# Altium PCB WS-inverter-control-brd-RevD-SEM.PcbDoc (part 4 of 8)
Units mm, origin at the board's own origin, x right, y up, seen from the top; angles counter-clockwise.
Board outline 270 x 105.92 mm, 6 copper layers (Top Layer, Int1 (Sign), Int2 (PWR), Int3 (GND), Int4 (Sign), Bottom Layer), stack 1.509 mm thick; 709 components, 375 nets, 2377 pads, 1332 vias.
Unrouted connection lines stored in the file: 55.
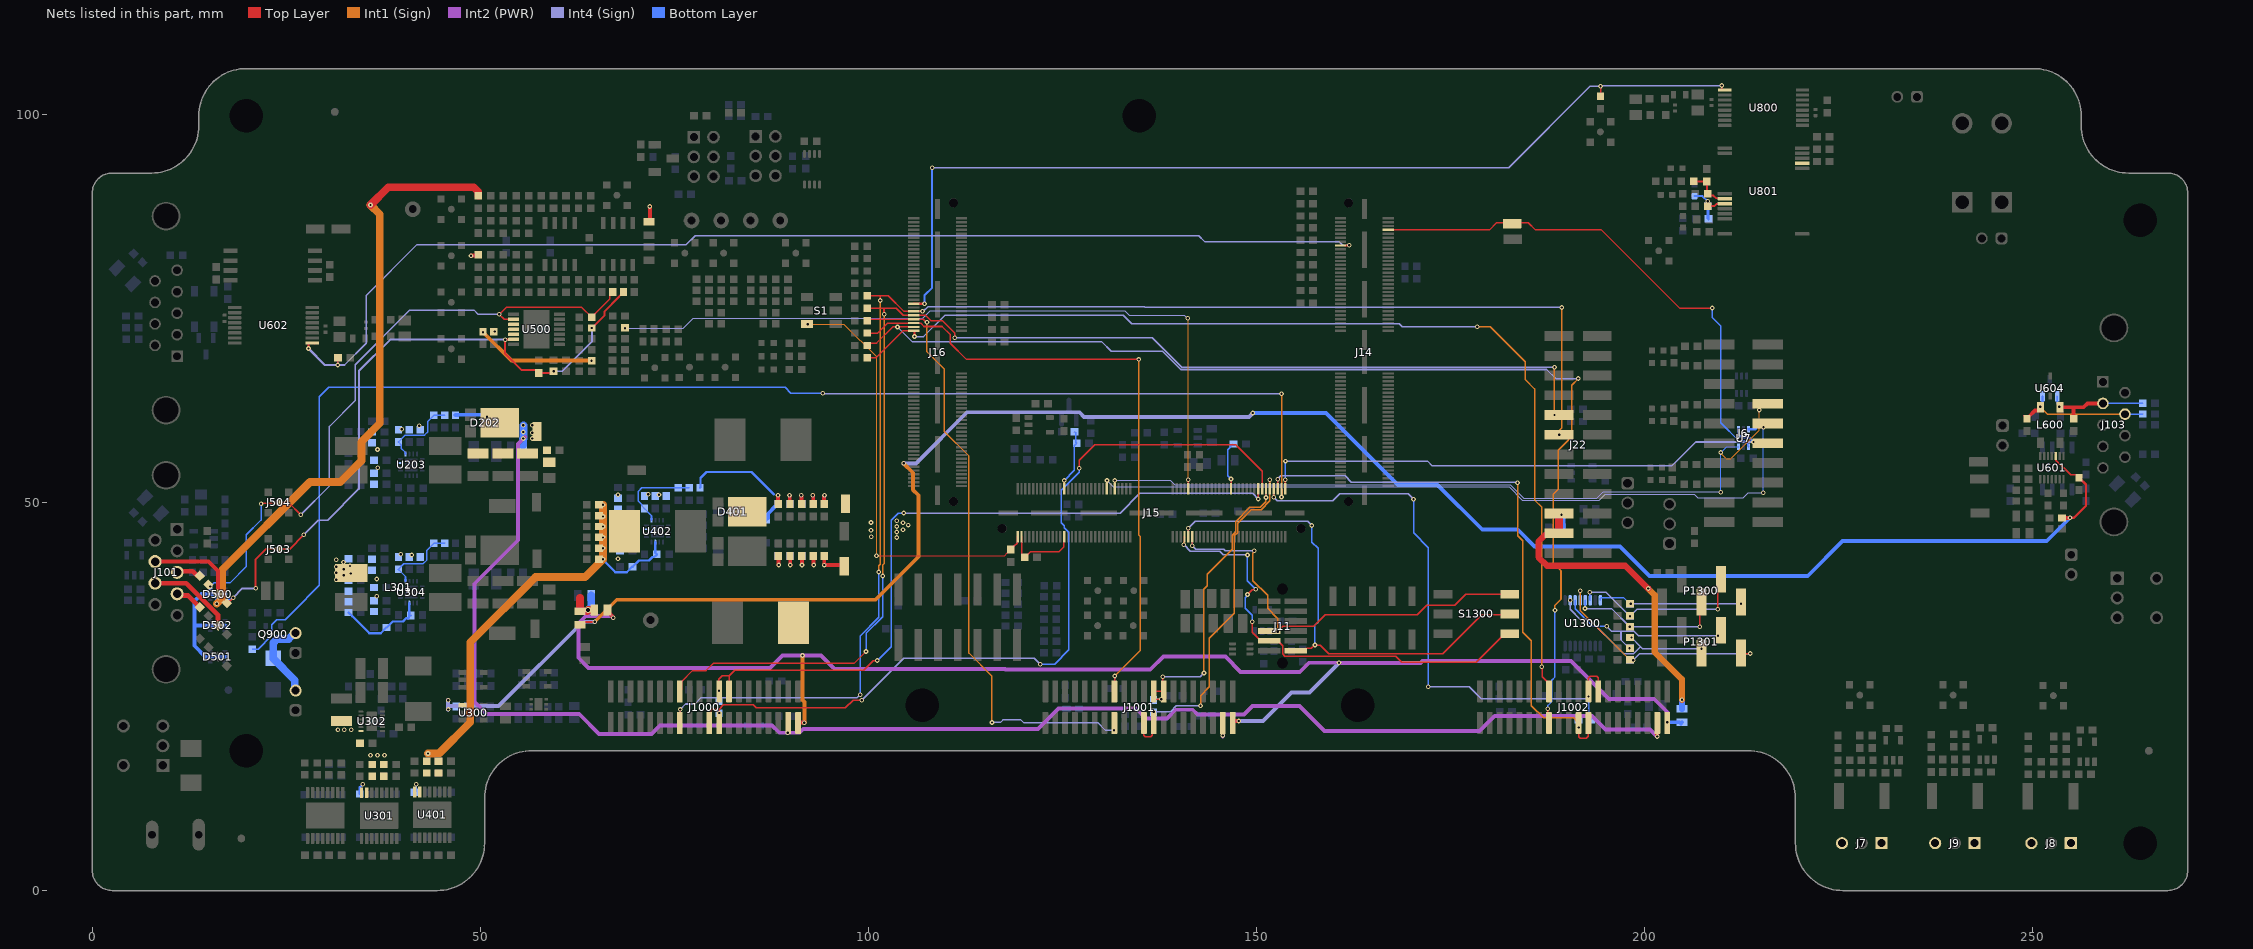
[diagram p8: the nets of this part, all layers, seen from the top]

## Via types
v1: diameter 0.6, hole 0.3, Top Layer to Bottom Layer, tented both sides, 1302 vias
v2: diameter 0.5, hole 0.2, Top Layer to Bottom Layer, 17 vias
v3: diameter 0.6, hole 0.3, Top Layer to Bottom Layer, 12 vias
v4: diameter 0.8, hole 0.5, Top Layer to Bottom Layer, tented both sides, 1 vias

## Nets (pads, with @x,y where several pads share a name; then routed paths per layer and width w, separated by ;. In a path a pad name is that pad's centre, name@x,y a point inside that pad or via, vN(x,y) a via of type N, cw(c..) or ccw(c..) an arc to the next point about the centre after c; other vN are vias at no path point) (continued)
+12V_L: C302.1 C303.1 C304.1 C305.1 C306.1 C307.1 C313.1 C317.1 C318.1 C319.1 C320.1 C321.1 C322.2 C328.1 C345.1 C611.2 L301.1 R300.2 R310.2 R619.2 Rjump12v.2 U300.1 U301.15 U301.16 U302.10 U302.12 U304.3 U601.10 | length 276.3
  Top Layer w0.25: Rjump12v.2@62.843,34.256 62.973,34.256 63.343,34.626 64.733,34.626 v1(64.743,34.636) ; U601.10@253,56 253.025,55.975 253.025,55.455 254.905,53.575 255.65,53.575 256,53.225 C611.2@256,53.2
  Top Layer w0.3: R619.2@253.8,48 v1@254.726,48 ; v1(254.843,48.036) 255.343,48.036 256.893,49.586 256.893,52.307 C611.2@256,53.2
  Top Layer w0.5: R619.2@253.8,48 253.825,48 254.807,48 v1(254.843,48.036)
  Int1 (Sign) w0.5: v1(64.743,34.636) 67.579,37.472 100.909,37.472 106.443,43.006 106.443,50.935 105.743,51.635 105.743,53.836 v1(104.543,55.036)
  Int4 (Sign) w0.5: v1(45.843,23.336) 45.843,23.754 ; v1(45.843,24.536) 45.843,23.754 ; v1(64.743,34.636) 63.233,34.636 52.351,23.754 45.843,23.754 ; v1(104.543,55.036) 106.127,55.036 112.715,61.625 127.209,61.625 127.797,61.036 149.043,61.036 v1(149.543,61.536)
  Bottom Layer w0.3: C317.1@33,35.825 33.025,35.825 33.489,35.361 33.5,35.361 35.699,33.161 37.15,33.161 37.875,33.886 R310.2@37.9,33.886 37.925,33.886 38.712,34.674 40.021,34.674 40.434,35.086 40.718,35.086 40.807,35.175 40.807,35.436 C328.1@41.043,35.436 ; R300.2@34.457,12.443 34.457,13.292 v1(34.858,13.693) ; C328.1@40.85,35.493 U304.3@40.85,37.05
  Bottom Layer w0.5: v1(149.543,61.536) 158.943,61.536 168.221,52.259 173.345,52.259 179.107,46.496 183.68,46.496 185.84,44.336 196.843,44.336 200.643,40.536 221.043,40.536 225.543,45.036 251.843,45.036 v1(254.843,48.036)
  other v1: 35.843,17.436 36.743,17.436 37.643,17.436 31.643,20.736 32.443,20.736 33.343,20.736 31.443,40.036 32.404,40.625 33.309,40.846 31.443,40.936 32.404,41.385 31.443,41.736 33.202,41.825 32.357,42.29 31.443,42.636
+12V_LEM: C406.1 C407.1 C408.1 C409.1 C413.1 C414.1 C415.1 C416.1 C417.1 C418.1 C429.1 L400.1 R400.2 R425.2 U401.15 U401.16 U402.3 | length 57.4
  Int1 (Sign) w1: v1(43.256,17.656) 44.663,17.656 48.7,21.694 48.7,31.994 57.095,40.389 63.489,40.389 v1(65.8,42.7) v1(65.8,44.1) v1(65.8,49.7)
  Bottom Layer w0.2: R400.2@41.5,12.643 41.749,12.892 v1(41.749,13.703)
  Bottom Layer w0.3: v1(65.8,42.7) 65.857,42.643 65.857,42.553 67.399,41.011 68.85,41.011 69.575,41.736 R425.2@69.6,41.736 69.625,41.736 70.425,42.536 71.744,42.536 72.184,42.976 72.242,42.976 72.253,42.986 72.418,42.986 C429.1@72.743,43.311 ; U402.3@72.55,44.9 72.55,43.53 C429.1@72.743,43.336
  other v1: 65.8,45.5 65.8,46.9 65.8,48.204
+15V: C412.1 C421.1 C422.1 C423.2 C424.2 C425.2 C426.2 C427.2 C428.2 C504.1 C505.1 D401.3 D500.2 D500.5 D501.2 D501.5 D502.2 D502.5 J7.1 J8.1 J9.1 R426.2 R505.2 R530.1 R541.1 R549.1 TP401.1 U500.10 U500.11 U500.12 | length 137.8
  Top Layer w0.5: v1(48.802,81.795) 48.843,81.836 49.663,81.836 R530.1@49.738,81.911 ; v1(64.32,68.279) 64.337,68.279 R505.2@64.344,68.286 ; R541.1@71.738,86.161 71.843,86.266 v1(71.843,88.136) ; v1(88.343,50.936) 88.362,50.917 88.362,49.838 C428.2@88.4,49.8 ; v1(89.843,50.936) 89.862,50.917 89.862,49.838 C427.2@89.9,49.8 ; v1(91.343,50.936) 91.343,50.909 91.4,50.853 C426.2@91.4,49.8 ; v1(92.843,50.936) 92.843,50.909 92.9,50.853 C422.1@92.9,49.8 ; C421.1@94.3,49.8 94.3,50.866 94.343,50.909 v1(94.343,50.936)
  Top Layer w1: v1(35.843,88.336) 38.143,90.636 49.153,90.636 49.738,90.051 R549.1@49.738,89.511
  Int2 (PWR) w0.5: v1@64.313,68.286 v1(64.32,68.279)
  Int1 (Sign) w0.5: v1(50.343,71.933) 53.997,68.279 v1(64.32,68.279)
  Int1 (Sign) w1: v1(16.036,36.943) 16.746,37.653 16.746,41.339 28.043,52.636 31.943,52.636 34.675,55.368 34.675,57.842 37.043,60.21 37.043,87.136 v1(35.843,88.336)
  Bottom Layer w0.3: R426.2@78.3,51.9 78.356,51.956 78.356,53.149 79.143,53.936 84.943,53.936 87.843,51.036
  Bottom Layer w0.5: v1(16.036,36.943) 16.036,38.123 16.113,38.199 ; D501.5@17.1,30.119 D501.2@15.2,30.119 15.193,30.112 14.567,30.112 13.143,31.536 13.143,34.159 ; D502.5@17.1,34.159 D502.2@15.2,34.159 13.143,34.159 ; D500.5@17.1,38.199 16.113,38.199 ; C412.1@86.8,47.8 86.825,47.8 87.05,48.025 87.05,48.545 88.055,49.55 88.175,49.55 88.4,49.775 C423.2@88.4,49.8 ; 13.143,34.159 13.143,37.312 14.03,38.199 D500.2@15.2,38.199 16.113,38.199
  other v1: 51.843,72.033
+24V_H: C219.1 C230.1 C231.1 C232.1 C233.1 C234.1 D202.3 J1000.37 J1001.37 J1002.37 R244.2 TP201.1 | length 212.2
  Top Layer w0.5: v1(89.627,20.329) 89.646,20.348 89.646,21.566 J1000.37@89.669,21.588 ; v1(145.669,19.976) J1001.37@145.669,21.588 ; v1(201.643,19.836) 201.643,21.563 J1002.37@201.669,21.588
  Int2 (PWR) w0.5: v1@55.743,58.436 v1(55.543,58.236) 54.843,57.536 54.843,45.136 49.243,39.536 49.243,24.282 50.786,22.739 62.741,22.739 65.293,20.186 72.029,20.186 73.129,21.286 87.581,21.286 88.538,20.329 91.136,20.329 91.612,20.806 121.872,20.806 124.514,23.448 134.514,23.448 135.775,22.186 138.493,22.186 139.605,23.298 141.8,23.298 142.393,22.704 145.643,22.704 ; v1@145.669,19.862 v1(145.669,19.976) 145.669,22.679 145.643,22.704 ; v1(201.643,19.836) 200.727,20.753 194.978,20.753 193.257,22.473 180.704,22.473 178.767,20.536 158.763,20.536 155.531,23.768 149.475,23.768 148.411,22.704 145.643,22.704
  Bottom Layer w0.5: R244.2@46.8,61.25 47.123,61.25 47.173,61.3 50.58,61.3 v1(50.843,61.036)
  Bottom Layer w1: C219.1@55.5,57.4 55.5,58.193 v1(55.543,58.236) v1(55.543,59.086) v1(55.543,59.936)
  other v1: 56.7,58.249 56.7,58.993 56.7,59.934
+24V_L: R114.2 Rjump12v.1 Rjumppre.1 | length 5.7
  Top Layer w1: 62.843,37.736 Rjump12v.1@62.843,35.986 62.848,35.991 63.748,35.991 v4(63.893,36.136) R114.2@64.663,36.136
  Bottom Layer w1: v4(63.893,36.136) 64.288,36.531 64.288,38.031 Rjumppre.1@64.293,38.036
+24V_L_SF: J1000.39 J1001.39 J1002.39 R113.1 R114.1 | length 187.7
  Top Layer w0.5: R114.1@66.393,36.136 66.393,35.931 67.104,35.221 v1(67.104,35.161) ; J1000.39@90.939,21.588 90.987,21.636 v1(91.743,21.636) ; J1001.39@146.939,21.588 146.939,21.716 147.059,21.836 v1(147.743,21.836) ; J1002.39@202.896,21.751 v1(202.961,21.686)
  Int2 (PWR) w0.5: v1(67.104,35.161) 66.909,35.356 63.582,35.356 62.643,34.417 62.643,29.987 63.938,28.692 87.337,28.692 88.922,30.276 v1(91.504,30.276) 93.872,30.276 95.612,28.536 117.601,28.536 117.682,28.455 136.324,28.455 138.004,30.136 146,30.136 147.961,28.175 155.587,28.175 156.758,29.346 v1@160.643,29.346 ; v1(160.643,29.336) 171.133,29.336 171.393,29.596 190.518,29.596 195.452,24.663 201.266,24.663 202.961,22.968 v1(202.961,21.686)
  Int1 (Sign) w0.5: v1(91.504,30.276) 91.504,24.538 91.743,24.298 v1(91.743,21.636)
  Int4 (Sign) w0.5: v1(147.743,21.836) 150.843,21.836 154.543,25.536 156.843,25.536 v1(160.643,29.336)
  Bottom Layer w0.5: v1(202.961,21.686) 204.543,21.686 204.693,21.536 R113.1@204.843,21.686
+24V_L_SMCU: C17.1 C18.1 J22.19 J22.21 R113.2 | length 42.2
  Top Layer w0.8: J22.21@188.993,46.036 188.758,45.801 187.176,45.801 186.334,44.96 186.334,42.972 187.447,41.859 197.536,41.859 v1(200.482,38.913)
  Top Layer w1: J22.21@188.993,46.036 J22.19@188.993,48.418 ; J22.19@189.312,48.418 v1(189.312,48.431)
  Int1 (Sign) w0.8: v1(200.482,38.913) 201.328,38.067 201.328,30.727 204.826,27.229 v1@204.826,24.571
  Bottom Layer w0.18: R113.2@204.829,23.43 R113.2@204.843,23.416
  Bottom Layer w0.8: R113.2@204.829,23.43 v1(204.829,24.567)
  Bottom Layer w1: v1(189.312,48.431) C18.1@189.318,48.436 ; C17.1@189.318,46.836 C18.1@189.318,48.431
-15V: C435.2 C436.2 C437.1 C438.1 C439.1 C440.1 C441.1 C442.1 J7.3 J8.3 J9.3 L402.2 TP404.1 | length 8.6
  Top Layer w0.5: C442.1@88.4,43.1 88.424,43.076 88.424,41.956 v1(88.443,41.936) ; C441.1@89.9,43.1 89.924,43.076 89.924,41.956 v1(89.943,41.936) ; C440.1@91.4,43.1 91.424,43.076 91.424,41.956 v1(91.443,41.936) ; C436.2@92.9,43.1 92.924,43.076 92.924,41.956 v1(92.943,41.936) ; C435.2@94.3,43.1 94.309,43.091 v1(94.309,41.935) 96.765,41.935 TP404.1@96.9,41.8
  Int2 (PWR) w1: J9.3@237.443,6.083 J9.3@237.463,6.103
  other v1: 103.652,45.489 100.352,45.589 103.652,46.189 100.343,46.436 104.452,46.489 103.646,46.916 105.152,47.089 104.452,47.389 100.328,47.416 103.662,47.647
AD_H_A: J16.52 J22.9 J1000.16 R43.2 | length 170.2
  Top Layer w0.2: J1000.16@75.699,25.653 75.969,25.924 75.969,26.962 77.343,28.336 79.088,28.336 80.058,29.306 98.203,29.306 v1(99.698,30.801) ; R43.2@99.843,75.036 102.014,75.036 ; v1(102.043,74.236) 102.014,74.266 102.014,75.036 ; J16.52@105.838,74.122 104.504,74.122 103.6,75.026 102.14,75.026 102.129,75.036 102.014,75.036 ; J16.52@105.843,74.126 107.36,74.126 108.096,73.39 109.581,73.39 111.143,71.829 v1(111.143,71.236) ; v1(188.401,61.278) J22.9@188.443,61.236
  Int1 (Sign) w0.2: v1(101.843,40.536) 101.843,41.936 102.043,42.136 v1(102.043,74.236) ; v1(188.401,61.278) v1(188.401,67.436)
  Int4 (Sign) w0.2: v1(111.143,71.236) 136.572,71.236 140.372,67.436 v1(188.401,67.436)
  Bottom Layer w0.2: v1(99.698,30.801) 99.698,33.139 101.843,35.284 v1(101.843,40.536)
AD_H_B: J16.56 J1001.16 R44.2 | length 82.4
  Top Layer w0.2: R44.2@99.843,71.836 101.207,71.836 102.493,73.122 J16.56@105.838,73.122 105.845,73.115 106.733,73.115 107.167,72.681 109.498,72.681 110.543,71.636 110.543,70.526 112.633,68.436 v1(134.843,68.436) ; J1001.16@131.699,25.653 131.743,25.698 v1(131.743,27.636)
  Int1 (Sign) w0.2: v1(131.743,27.636) 135.043,30.936 135.043,45.605 134.843,45.805 v1(134.843,68.436)
AD_H_C: J16.60 J1002.16 R45.2 | length 134.3
  Top Layer w0.2: R45.2@99.843,68.636 100.985,68.636 104.471,72.122 J16.60@105.838,72.122 105.887,72.122 105.939,72.069 v1(105.939,71.383) ; v1(186.756,28.852) 186.82,28.788 186.82,27.56 187.543,26.836 187.543,25.809 J1002.16@187.699,25.653
  Int1 (Sign) w0.2: v1(178.443,72.636) 180.133,72.636 184.643,68.126 184.643,65.836 185.843,64.636 185.843,50.336 186.756,49.423 v1(186.756,28.852)
  Int4 (Sign) w0.2: v1(105.939,71.383) 107.116,71.383 109.876,74.142 132.837,74.142 133.943,73.036 168.4,73.036 168.8,72.636 v1(178.443,72.636)
AD_L_A: J16.50 J22.11 J1000.15 R46.2 | length 185.4
  Top Layer w0.2: J1000.15@75.699,21.588 75.743,21.633 v1(75.743,23.336) ; R46.2@99.843,76.636 101.543,76.636 ; v1(101.543,76.036) 101.543,76.636 ; v1(106.974,74.65) 106.96,74.636 105.852,74.636 J16.50@105.838,74.622 104.58,74.622 102.566,76.636 101.543,76.636 ; J22.11@188.993,58.736 v1(189.016,58.736)
  Int1 (Sign) w0.2: v1(101.343,41.036) 101.343,41.836 101.543,42.036 v1(101.543,76.036) ; v1(189.016,58.736) 189.016,59.276 189.343,59.603 v1(189.343,75.136)
  Int4 (Sign) w0.2: v1(75.743,23.336) 76.443,24.036 77.643,24.036 78.443,24.836 98.543,24.836 v1(98.943,25.236) ; v1(106.974,74.65) 107.082,74.65 107.669,75.236 135.55,75.236 135.65,75.136 v1(189.343,75.136)
  Bottom Layer w0.2: v1(98.943,25.236) 98.943,32.808 101.343,35.208 v1(101.343,41.036)
AD_L_B: J16.54 J1001.15 R47.2 | length 79.8
  Top Layer w0.2: R47.2@99.843,73.436 100.029,73.622 J16.54@105.276,73.622 ; J16.54@105.838,73.622 107.08,73.622 107.466,73.236 v1(107.543,73.236) ; v1(131.653,20.635) 131.699,20.681 J1001.15@131.699,21.588
  Int1 (Sign) w0.2: v1(107.543,73.236) 107.543,69.436 109.747,67.232 109.747,59.183 112.953,55.977 112.953,30.595 115.889,27.659 115.889,21.656 v1(115.924,21.656)
  Int4 (Sign) w0.2: v1(115.924,21.656) 117.017,21.656 117.347,21.986 119.649,21.986 119.998,21.636 129.543,21.636 130.545,20.635 v1(131.653,20.635)
AD_L_C: J16.58 J1002.15 R48.2 | length 144.2
  Top Layer w0.2: R48.2@99.843,70.236 100.147,70.54 101.047,70.54 103.129,72.622 v1(103.743,72.622) J16.58@105.573,72.622 ; v1(187.543,23.416) 187.543,21.744 J1002.15@187.699,21.588
  Int1 (Sign) w0.2: v1(188.471,36.112) 188.471,36.764 189.25,37.543 189.25,41.219 188.253,42.216 188.253,51.049 188.899,51.696 188.899,56.743 190.629,58.472 190.629,65.122 v1(191.489,65.982)
  Int4 (Sign) w0.2: v1(103.743,72.622) 105.629,70.736 130.054,70.736 131.298,69.493 137.887,69.493 139.343,68.036 139.348,68.036 140.248,67.136 187.389,67.136 188.589,65.936 191.443,65.936 v1(191.489,65.982)
  Bottom Layer w0.2: v1(187.543,23.416) 187.563,23.436 187.563,23.845 188.069,24.351 188.069,27.099 188.471,27.502 v1(188.471,36.112)
ADJ_NC_9: U801.3
AGND_A: C235.2 C238.2 C239.2 NT200.2 R247.1 R248.1 R249.1 R250.1 R251.1 U203.7
  other v1: 36.765,54.475 36.743,56.836 39.851,59.431 42.112,59.886
AGND_B: C337.2 C343.2 C344.2 NT300.2 R314.1 R315.1 R316.1 R317.1 R318.1 U304.7
  other v1: 36.643,37.936 36.643,40.136 41.143,43.236 39.743,43.336
AGND_C: C432.2 C444.2 C445.2 NT400.2 R428.1 R431.1 R432.1 R433.1 R434.1 U402.7
  other v1: 67.743,42.736 73.019,50.98 67.743,51.011 71.646,51.047
Alert_A: J6.5 J15.2 U7.1 | length 69
  Top Layer w0.18: J15.2@153.733,51.757 v1(153.733,52.926)
  Top Layer w0.3: v1(214.063,57.798) 214.169,57.692 J6.5@214.614,57.692
  Int4 (Sign) w0.2: v1(153.743,55.336) 172.043,55.336 172.638,54.742 203.548,54.742 206.605,57.798 v1(214.063,57.798)
  Bottom Layer w0.2: v1(153.733,52.926) 153.738,52.931 153.738,55.331 v1(153.743,55.336)
  Bottom Layer w0.3: U7.1@212.123,59.424 212.173,59.374 212.173,58.724 212.53,58.367 213.493,58.367 v1(214.063,57.798)
Alert_B: J6.6 J15.74 U7.3 | length 99.1
  Top Layer w0.18: J15.74@130.733,51.757 130.738,51.762 130.738,52.831 v1(130.743,52.836)
  Top Layer w0.3: J6.6@214.298,59.959 214.566,59.69 v1(215.346,59.69)
  Int4 (Sign) w0.16: v1(130.743,52.836) 131.581,51.999 182.581,51.999 184.283,50.296 194.197,50.296 194.937,51.036 206.443,51.036 206.843,50.636 212.743,50.636 213.356,51.249 v1(215.328,51.249)
  Bottom Layer w0.16: v1(215.328,51.249) 215.337,51.258 215.337,59.681 v1(215.346,59.69)
  Bottom Layer w0.3: U7.3@213.423,59.424 214.266,59.424 214.533,59.69 v1(215.346,59.69)
Alert_C: J6.7 J15.70 U7.6 | length 98.1
  Top Layer w0.18: J15.70@131.733,51.757 131.738,51.762 131.738,52.831 v1(131.743,52.836)
  Top Layer w0.3: v1(214.814,61.928) J6.7@214.814,62.392
  Int1 (Sign) w0.16: v1(209.843,56.436) 209.843,56.336 210.523,55.656 211.142,55.656 214.814,59.329 v1(214.814,61.928)
  Int4 (Sign) w0.16: v1(131.743,52.836) 138.885,52.836 139.463,52.259 182.721,52.259 184.423,50.556 193.885,50.556 194.692,51.363 209.816,51.363 v1(209.843,51.336)
  Bottom Layer w0.16: v1(209.843,51.336) v1(209.843,56.436) 210.581,57.174 U7.6@212.123,57.174
Alert_tmcs: J14.114 TP_alert.1 U7.4 | length 66.9
  Top Layer w0.2: J14.114@167.001,85.122 180.029,85.122 180.943,86.036 182.943,86.036 185.043,86.036 185.958,85.122 194.458,85.122 204.524,75.056 v1(208.743,75.056)
  Bottom Layer w0.2: v1(208.743,75.056) 208.743,73.836 209.843,72.736 209.843,60.288 212.198,57.933 212.936,57.933 213.323,57.547 213.323,57.278 U7.4@213.425,57.176
ALM_EXC+_5: C501.2 D500.6 J503.1 R500.2 R503.1 R509.1 R512.2 U500.13 | length 87.2
  Top Layer w0.25: R503.1@17.331,37.049 17.455,37.049 v1(18.143,37.736) ; v1(21.043,38.936) 21.043,42.682 22.361,44 J503.1@24,44 25.407,44 v1(27.248,45.841) ; U500.13@54.288,71.011 54.275,70.998 53.205,70.998 v1(53.191,70.984) 53.191,69.183 55.304,67.07 57.15,67.07 57.5,66.72 C501.2@57.5,66.7 R500.2@59.727,66.7 ; v1(64.369,72.486) 64.969,73.086 64.976,73.086 65.999,74.11 65.999,74.64 67.838,76.48 67.838,76.486 68.438,77.086 R512.2@68.438,77.111
  Int4 (Sign) w0.25: v1(18.143,37.736) 19.325,38.919 21.025,38.919 v1(21.043,38.936) ; v1(27.248,45.841) 29.119,47.713 30.319,47.713 34.35,51.743 34.35,66.943 38.391,70.984 v1(53.191,70.984) ; v1(59.438,66.911) 60.557,66.911 64.369,70.723 v1(64.369,72.486)
  Bottom Layer w0.25: D500.6@17.1,37.549 17.861,37.549 18.048,37.736 v1(18.143,37.736)
ALM_EXC-_5: D500.3 J504.1 R504.1 R508.1 R511.2 U500.9 | length 84.2
  Top Layer w0.2: R504.1@15.019,39.361 v1(15.2,39.18) ; v1(21.743,49.836) 21.82,49.913 23.913,49.913 J504.1@24,50 25.28,50 v1(26.843,48.436) ; U500.9@54.288,73.611 53.068,73.611 v1(52.443,74.236) 53.343,75.136 63.069,75.136 64.319,73.886 R508.1@64.344,73.886 64.369,73.886 64.744,74.261 64.744,74.286 66.668,76.211 66.668,76.741 R511.2@67.038,77.111
  Int4 (Sign) w0.2: v1(26.843,48.436) 30.543,52.136 30.543,59.798 33.872,63.127 33.872,67.765 40.895,74.788 49.183,74.788 49.735,74.236 v1(52.443,74.236)
  Bottom Layer w0.2: D500.3@15.2,38.849 v1(15.2,39.18) 15.703,39.683 17.789,39.683 19.843,41.736 19.843,45.836 21.743,47.736 v1(21.743,49.836)
Ambient_TEMP: C904.1 J15.96 R900.2 | length 8.2
  Top Layer w0.18: J15.96@125.233,51.757 v1(125.233,52.826)
  Bottom Layer w0.18: v1(125.233,52.826) 126.543,54.136 126.543,57.336 C904.1@126.843,57.636 126.693,57.786 126.693,58.986 R900.2@126.543,59.136
CAN_H_1: J103.7 L600.2 R600.2 R602.2 U604.2 | length 17.7
  Top Layer w0.2: R600.2@248.9,61.2 R600.2@248.925,61.2
  Top Layer w0.5: R600.2@249.3,60.8 249.525,61.025 249.525,61.05 250.325,61.85 250.85,61.85 251.05,62.05 L600.2@251.05,62.275 251.043,62.275 v1(250.984,62.335)
  Int1 (Sign) w0.2: v1(250.984,62.335) 251.933,61.385 J103.7@261.92,61.385
  Bottom Layer w0.2: v1(250.984,62.335) 250.984,62.427 251.293,62.736 U604.2@251.293,63.686 ; J103.7@261.92,61.385 264.179,61.385 R602.2@264.2,61.406
CAN_INH: J15.30 R616.1 | length 6.3
  Top Layer w0.18: J15.30@146.733,51.757 v1(146.733,53.022)
  Bottom Layer w0.18: v1(146.733,53.022) 146.301,53.454 146.301,56.794 146.633,57.126 146.633,57.151 147.018,57.536 R616.1@147.043,57.536
CAN_L_1: J103.2 L600.1 R605.1 R608.2 U604.1 | length 13.9
  Top Layer w0.2: v1(253.449,62.318) 253.507,62.318 L600.1@253.55,62.275
  Top Layer w0.5: L600.1@253.55,62.275 255.316,62.275 ; R608.2@255.3,60.8 255.3,62.259 255.316,62.275 ; J103.2@259.08,62.77 257.077,62.77 256.582,62.275 255.316,62.275
  Bottom Layer w0.2: U604.1@253.193,63.686 253.193,62.682 253.449,62.426 v1(253.449,62.318) ; J103.2@259.08,62.77 264.164,62.77 R605.1@264.2,62.806
CLKIN/OUTP/OUT: C6n.2 R6.1 R9.1 R11.1 U801.11 | length 7.3
  Top Layer w0.25: v1(208.15,88.803) R6.1@208.15,88.178 208.985,88.178 209.26,88.453 210.275,88.453 U801.11@210.375,88.553
  Bottom Layer w0.25: C6n.2@206.469,89.474 207.479,89.474 v1(208.15,88.803) R11.1@208.15,88.178
  Bottom Layer w0.381: R11.1@208.15,88.178 208.196,88.132 208.196,86.588 R9.1@208.243,86.542
COS+_1: J101.8 R545.2 | length 11.2
  Top Layer w0.6: J101.8@8.08,39.615 12.085,39.615 16.182,35.518 16.182,34.405 16.2,34.387 R545.2@16.2,34.14
COS-_1: J101.4 R538.2 | length 3.6
  Top Layer w0.6: J101.4@10.92,38.23 11.129,38.021 12.319,38.021 R538.2@13.834,36.506
DAC_A_16: J15.119 R7.2 S1.4 | length 56
  Top Layer w0.16: S1.4@92.093,72.986 v1(92.193,72.986) ; v1(101.043,43.132) 117.539,43.132 117.923,43.516 117.948,43.516 118.343,43.911 R7.2@118.343,43.936
  Top Layer w0.18: R7.2@118.343,43.936 118.343,43.961 118.728,44.346 118.753,44.346 119.171,44.764 119.171,45.522 J15.119@119.221,45.573
  Int1 (Sign) w0.16: v1(92.193,72.986) 96.837,72.986 101.049,68.775 101.049,43.138 v1(101.043,43.132)
DAC_B_16: J15.95 J15.117 R18.2 | length 9.8
  Top Layer w0.18: J15.117@119.733,45.585 119.733,43.321 120.118,42.936 R18.2@120.143,42.936
  Top Layer w0.2: R18.2@120.143,42.936 120.168,42.936 120.868,43.636 124.543,43.636 125.181,44.274 125.181,45.532 J15.95@125.233,45.585
DOUT/OUTN/REFIN: R2.1 R12.1 R25.2 U801.10 | length 5.8
  Top Layer w0.25: R12.1@206.35,91.378 R25.2@208.05,91.378 208.05,89.878 208.377,89.551 208.879,89.551 209.227,89.203 U801.10@210.375,89.203
ECAP_B1_13: C1302.1 P1300.1 R1300.1 U1300.16 | length 18.8
  Top Layer w0.2: R1300.1@198.143,36.936 v1(198.218,36.936)
  Int4 (Sign) w0.2: v1(198.218,36.936) v1(212.443,36.936)
  Bottom Layer w0.2: U1300.16@194.325,37.4 194.325,37.636 194.44,37.751 197.304,37.751 198.118,36.936 C1302.1@198.143,36.936 v1(198.218,36.936)
ECAP_B2_13: C1303.1 P1300.2 R1301.1 U1300.14 | length 23.3
  Top Layer w0.2: v1(198.143,35.336) R1301.1@198.143,35.4 ; v1(209.443,36.236) 209.443,39.656 P1300.2@209.883,40.096
  Int4 (Sign) w0.2: v1(192.943,38.436) 195.043,38.436 v1(198.143,35.336) 199.043,36.236 v1(209.443,36.236)
  Bottom Layer w0.2: v1(192.943,38.436) 192.98,38.4 192.98,37.445 U1300.14@193.025,37.4
ECAP_B3_13: C1304.1 P1300.3 R1302.1 U1300.13 | length 20.1
  Top Layer w0.2: v1(198.107,34) R1302.1@198.143,34 ; v1(207.107,34) 207.107,36.94 P1300.3@207.343,37.176
  Int4 (Sign) w0.2: v1(192.343,36.336) 195.77,36.336 v1(198.107,34) v1(207.107,34)
  Bottom Layer w0.2: v1(192.343,36.336) 192.375,36.368 U1300.13@192.375,37.4
EQEP_A_13: C1305.1 P1301.1 R1305.1 U1300.12 | length 29.9
  Top Layer w0.2: P1301.1@212.423,30.599 212.486,30.536 v1(213.643,30.536)
  Int1 (Sign) w0.2: v1(191.737,38.618) 191.737,36.094 198.129,29.702 198.549,29.702 v1(198.563,29.688)
  Int4 (Sign) w0.2: v1(191.737,38.618) v1@191.737,38.63 ; v1(198.563,29.688) 199.412,30.536 v1(213.643,30.536)
  Bottom Layer w0.2: U1300.12@191.725,37.4 191.725,38.607 v1(191.737,38.618)
EQEP_B_13: C1306.1 P1301.2 R1306.1 U1300.11 | length 23.7
  Top Layer w0.2: v1(209.487,32.808) P1301.2@209.503,32.825
  Int4 (Sign) w0.2: v1(195.143,34.036) 195.757,33.422 196.983,33.422 ; v1(198.08,31.2) 196.983,32.296 196.983,33.422 ; v1(209.487,32.808) 199.274,32.808 198.66,33.422 196.983,33.422
  Bottom Layer w0.2: U1300.11@191.075,37.4 191.075,36.305 193.345,34.034 195.141,34.034 v1(195.143,34.036)
EQEP_I_13: C1307.1 P1301.3 R1307.1 U1300.10 | length 22.8
  Top Layer w0.2: R1307.1@198.143,32.6 v1(198.324,32.6)
  Int4 (Sign) w0.2: v1(190.443,37.418) 190.443,36.235 191.742,34.936 192.894,34.936 197.297,30.533 198.622,30.533 199.507,31.418 ; v1(198.324,32.6) 199.507,31.418 ; v1(207.343,31.136) 199.788,31.136 199.507,31.418
  Bottom Layer w0.2: U1300.10@190.425,37.4 v1(190.443,37.418)
EXC+_1: J101.7 R503.2 | length 11.6
  Top Layer w0.5: J101.7@8.08,42.385 14.965,42.385 16.182,41.168 16.182,38.198 R503.2@16.2,38.18
EXC-_1: J101.3 R504.2 | length 3.2
  Top Layer w0.6: J101.3@10.92,41 11.069,41.149 12.929,41.149 13.515,40.563 13.817,40.563 R504.2@13.834,40.546
EXC_OC_OT: J15.52 R551.1 | length 95.9
  Top Layer w0.18: J15.52@141.233,51.757 v1(141.233,52.926)
  Top Layer w0.5: v1(68.638,72.447) R551.1@68.638,72.511
  Int1 (Sign) w0.16: v1(141.143,73.736) 141.188,73.691 141.188,52.971 v1(141.233,52.926)
  Int4 (Sign) w0.16: v1(68.638,72.447) 76.154,72.447 77.443,73.736 107.021,73.736 107.965,74.68 133.059,74.68 133.583,74.156 140.686,74.156 141.106,73.736 v1(141.143,73.736)
FAN-CTRL: D900.2 J109.2 J110.2 Q900.3 | length 10.8
  Bottom Layer w1: J110.2@26.2,25.77 26.095,25.875 26.095,27.105 D900.2@23.3,29.9 Q900.3@23.3,31.9 23.823,32.423 25.304,32.423 26.051,33.17 J109.2@26.2,33.17
FAN_PWM: J15.4 R906.1 | length 176.4
  Top Layer w0.18: v1(153.233,50.709) J15.4@153.233,51.757
  Int1 (Sign) w0.18: v1(153.233,50.709) v1(153.233,63.995)
  Int4 (Sign) w0.18: v1(94.13,64.082) 94.174,64.038 153.189,64.038 v1(153.233,63.995)
  Bottom Layer w0.18: R906.1@20.6,31.1 21.353,31.1 23.123,32.87 23.123,34.274 23.741,34.892 24.828,34.892 25.943,36.007 29.243,39.307 29.243,63.637 30.442,64.836 89.265,64.836 90.019,64.082 v1(94.13,64.082)
FB_15V_4: C433.2 R430.1 R431.2 U402.9 | length 11.2
  Bottom Layer w0.2: U402.9@72.05,47.7 72.05,48.305 71.143,49.211 R431.2@71.143,49.236 70.768,49.611 70.768,49.766 70.331,50.204 70.331,51.42 70.81,51.9 R430.1@75.5,51.9 C433.2@76.9,51.9
FB_HS_2: C236.2 R246.1 R248.2 U203.9 | length 10.1
  Bottom Layer w0.2: U203.9@40.35,56.25 40.35,56.43 39.813,56.967 39.813,57.416 R248.2@39.443,57.786 39.443,57.811 40.318,58.686 42.798,58.686 43.212,59.1 43.212,60.437 44,61.225 R246.1@44,61.25 C236.2@45.4,61.25
FB_LS_3: C336.2 R313.1 R315.2 U304.9 | length 10
  Bottom Layer w0.2: U304.9@40.35,39.85 40.35,40.455 39.443,41.361 R315.2@39.443,41.386 39.443,41.411 40.128,42.096 42.608,42.096 43.117,42.605 43.117,43.842 44,44.725 R313.1@44,44.75 C336.2@45.4,44.75
FLT_AMCsupply5V: J16.46 R800.1 U800.1 | length 127.7
  Top Layer w0.2: R800.1@194.343,102.336 v1(194.343,103.636) ; v1(209.943,103.736) 209.943,103.258 210.048,103.153 U800.1@210.35,103.153
  Top Layer w0.3: J16.46@105.838,75.622 v1(107.229,75.622)
  Int4 (Sign) w0.2: v1(108.222,93.147) 182.51,93.147 192.999,103.636 v1(194.343,103.636) 194.393,103.686 209.893,103.686 v1(209.943,103.736)
  Bottom Layer w0.25: v1(107.229,75.622) 107.229,76.722 108.203,77.697 108.203,93.129 v1(108.222,93.147)
FLT_CANSupply: J14.105 R620.1 U602.1 | length 149.1
  Top Layer w0.2: v1(31.626,67.72) 31.626,68.619 R620.1@31.643,68.636
  Top Layer w0.25: U602.1@28.343,70.561 28.569,70.561 U602.1@28.649,70.481 ; J14.105@161.352,83.118 161.368,83.133 161.954,83.133 v1(161.965,83.145)
  Top Layer w0.3: v1(27.843,69.836) 27.843,70.506 27.898,70.561 U602.1@28.343,70.561
  Int4 (Sign) w0.2: v1(31.626,67.72) 32.502,67.72 35.295,70.514 35.295,76.689 41.843,83.236 76.531,83.236 77.677,84.383 142.561,84.383 143.317,83.626 160.634,83.626 160.93,83.33 161.115,83.145 v1(161.965,83.145)
  Int4 (Sign) w0.3: v1(27.843,69.836) 29.959,67.72 v1(31.626,67.72)
FSITX_CLK: J11.7 J15.49 S1300.3 | length 54.2
  Top Layer w0.18: v1(141.733,44.446) J15.49@141.733,45.585 ; J11.7@151.65,33.448 152.74,33.448 153.371,34.078 157.385,34.078 158.843,35.536 170.72,35.536 171.925,36.742 175.548,36.742 176.983,38.176 S1300.3@182.643,38.176
  Int1 (Sign) w0.18: v1(149.741,43.781) 149.741,43.667 149.543,43.469 149.543,40.436 149.543,39.943 151.443,38.043 151.443,36.351 152.743,35.051 v1(152.743,33.336)
  Int4 (Sign) w0.18: v1(141.733,44.446) 142.179,44 145.794,44 146.013,43.781 v1(149.741,43.781)
FSITX_D0: J11.9 J15.53 S1300.1 | length 58.5
  Top Layer w0.18: v1(140.643,44.536) 140.688,44.581 140.688,45.54 J15.53@140.733,45.585 ; v1(148.843,38.136) 149.459,38.752 149.853,38.752 v1(149.933,38.832) ; v1(149.443,34.636) 149.443,33.295 150.56,32.178 J11.9@151.65,32.178 J11.9@152.035,32.178 ; J11.9@152.035,32.36 J11.9@152.035,32.178 ; S1300.1@182.643,33.096 181.988,33.096 178.328,29.436 168.743,29.436 167.962,30.218 153.627,30.218 153.365,30.48 153.365,31.553 152.74,32.178 J11.9@152.035,32.178
  Int4 (Sign) w0.18: v1(140.643,44.536) 140.682,44.536 141.498,43.72 145.259,43.72 145.743,43.236 v1(148.843,43.236)
  Bottom Layer w0.18: v1(148.843,38.136) 148.843,38.05 148.551,37.757 148.551,36.392 149.443,35.5 v1(149.443,34.636) ; v1(148.843,43.236) 148.843,39.922 v1(149.933,38.832)
FSITX_D1: J11.12 J15.51 S1300.2 | length 64
  Top Layer w0.18: J15.51@141.233,45.585 v1(141.233,46.697) ; J11.12@155.08,30.908 156.17,30.908 156.45,31.188 157.095,31.188 v1(157.543,31.636) 158.226,31.636 159.326,30.536 174.024,30.536 179.024,35.537 182.543,35.537 S1300.2@182.643,35.636
  Int4 (Sign) w0.18: v1(141.233,46.697) 141.233,46.726 141.263,46.726 142.134,47.597 152.097,47.597 152.108,47.586 156.593,47.586 v1(157.143,47.036)
  Bottom Layer w0.18: v1(157.143,47.036) 157.143,44.873 157.943,44.073 157.943,34.573 157.543,34.173 v1(157.543,31.636)
GDAH: J15.16 J1000.24 J1000.26 R1013.2 | length 95.4
  Top Layer w0.18: J1000.24@80.78,25.761 v1(80.743,25.724) 80.743,27.243 81.149,27.649 82.049,27.649 ; J1000.26@82.049,25.653 82.049,27.649 ; v1(101.143,29.636) 100.643,29.636 99.413,28.406 82.806,28.406 82.049,27.649 ; v1(150.233,50.446) J15.16@150.233,51.757
  Int4 (Sign) w0.18: v1(104.543,48.636) 132.456,48.636 134.989,51.169 149.511,51.169 v1(150.233,50.446)
  Bottom Layer w0.18: R1013.2@80.743,24.436 v1(80.743,25.724) ; v1(101.143,29.636) 102.933,31.426 102.933,47.726 103.843,48.636 v1(104.543,48.636)
GDAL: J15.14 J1000.21 J1000.23 R1013.1 | length 107.8
  Top Layer w0.18: J1000.21@79.509,21.588 79.7,21.779 79.7,23.2 79.879,23.379 80.779,23.379 ; v1(80.779,22.872) 80.779,23.379 ; v1(99.143,24.536) 98.043,24.536 97.043,23.536 85.543,23.536 85.153,23.926 81.326,23.926 80.779,23.379 ; v1(127.182,54.402) 127.182,55.475 129.143,57.436 147.343,57.436 150.733,54.046 J15.14@150.733,51.757
  Top Layer w0.2: J1000.23@80.779,21.588 v1(80.779,22.872)
  Int4 (Sign) w0.18: v1(99.143,24.536) 104.543,29.936 121.343,29.936 v1(122.143,29.136)
  Bottom Layer w0.18: v1(80.779,22.872) R1013.1@80.843,22.936 ; v1(122.143,29.136) 123.987,29.136 125.843,30.993 125.843,46.141 125.263,46.721 125.263,47.016 124.864,47.416 124.864,51.553 127.182,53.872 v1(127.182,54.402)
GDBH: J15.12 J1001.24 J1001.26 R1014.2 | length 39.4
  Top Layer w0.18: v1(137.743,24.636) 137.059,24.636 136.779,24.916 J1001.24@136.779,25.653 J1001.26@138.049,25.653 137.943,25.759 v1(137.943,27.536) ; v1(151.233,50.641) J15.12@151.233,51.757
  Int1 (Sign) w0.18: v1(143.243,28.036) 143.243,38.836 143.652,39.245 143.652,40.745 146.886,43.979 146.886,45.81 147.319,46.244 147.319,47.514 149.172,49.367 150.474,49.367 151.233,50.126 v1(151.233,50.641)
  Int4 (Sign) w0.18: v1(137.943,27.536) 142.743,27.536 v1(143.243,28.036)
  Bottom Layer w0.18: R1014.2@136.743,24.611 136.768,24.636 v1(137.743,24.636)
  Bottom Layer w0.2: R1014.2@136.743,24.426 R1014.2@136.779,24.462
GDBL: J15.10 J1001.21 J1001.23 R1014.1 | length 47.1
  Top Layer w0.18: J1001.21@135.509,21.588 135.509,19.991 135.7,19.8 136.4,19.8 136.6,20 136.6,21.41 J1001.23@136.779,21.588 v1(136.779,23.043) ; J15.10@151.733,51.757 v1(151.733,52.926)
  Int1 (Sign) w0.18: v1(142.795,23.788) 142.795,25.109 143.932,26.245 143.932,32.511 147.166,35.745 147.166,45.694 147.599,46.128 147.599,47.331 149.356,49.087 150.594,49.087 151.733,50.226 v1(151.733,52.926)
  Int4 (Sign) w0.18: v1(136.779,23.043) 138.95,23.043 139.695,23.788 v1(142.795,23.788)
  Bottom Layer w0.18: R1014.1@136.759,23.063 v1(136.779,23.043)
GDCH: J15.8 J1002.24 J1002.26 R1012.2 | length 75.1
  Top Layer w0.18: v1(152.233,50.655) J15.8@152.233,51.757 ; v1(192.797,25.009) 192.779,25.027 J1002.24@192.779,25.653 192.779,27.374 193.04,27.635 193.827,27.635 194.049,27.414 J1002.26@194.049,25.653
  Int4 (Sign) w0.18: v1(152.233,50.655) 152.669,50.219 159.844,50.219 160.763,51.138 169.541,51.138 v1(170.243,50.436) ; v1(172.143,26.236) 177.443,26.236 179.001,24.679 192.424,24.679 192.754,25.009 v1(192.797,25.009)
  Bottom Layer w0.18: v1(170.243,50.436) 170.243,46.085 172.143,44.185 v1(172.143,26.236) ; v1(192.797,25.009) 192.797,22.303 R1012.2@193.1,22
GDCL: J15.6 J1002.21 J1002.23 R1012.1 | length 75.7
  Top Layer w0.18: J15.6@152.733,51.757 v1(152.733,52.991) ; J1002.21@191.509,21.588 191.509,19.828 191.73,19.607 192.517,19.607 192.779,19.868 J1002.23@192.779,21.588
  Int1 (Sign) w0.18: v1(183.643,52.536) 183.643,45.743 184.343,45.043 184.343,33.269 185.443,32.169 185.443,23.836 187.043,22.236 190.904,22.236 191.5,21.64 191.5,21.045 v1(191.529,21.016)
  Int4 (Sign) w0.18: v1(152.733,52.991) 153.159,53.416 161.418,53.416 162.198,52.636 183.543,52.636 v1(183.643,52.536)
  Bottom Layer w0.18: R1012.1@191.5,22 191.529,21.971 v1(191.529,21.016)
